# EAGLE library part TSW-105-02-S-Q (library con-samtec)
THROUGH-HOLE .025" SQ POST HEADER Source: Samtec TSW.pdf
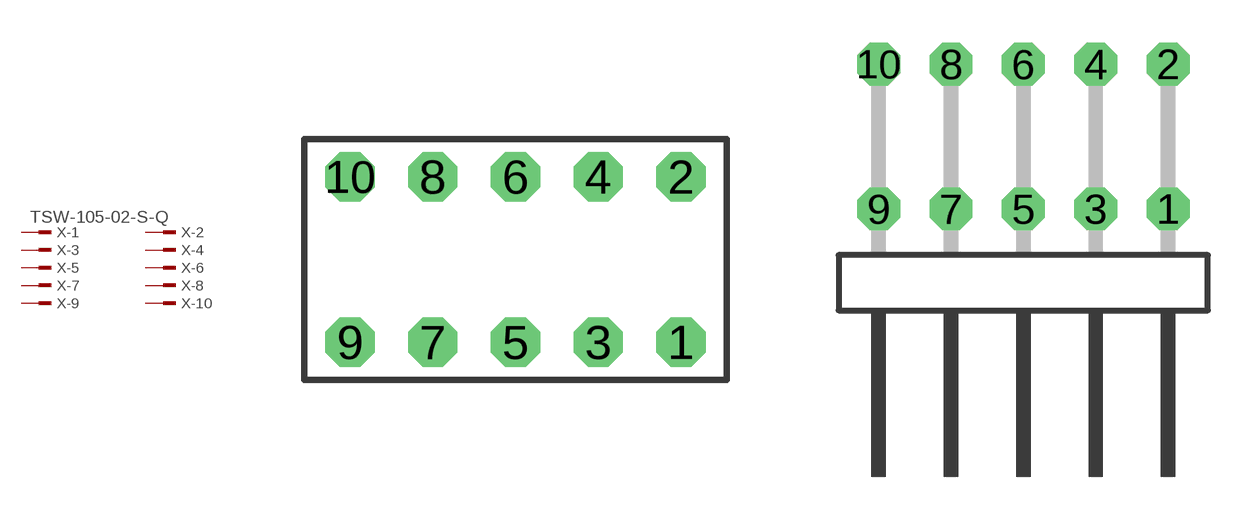
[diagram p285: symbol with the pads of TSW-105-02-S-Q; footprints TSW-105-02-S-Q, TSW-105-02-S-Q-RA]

Designator prefix X; gates -1=MPINV -2=MPIN -3=MPIN -4=MPIN -5=MPIN -6=MPIN -7=MPIN -8=MPIN -9=MPIN -10=MPIN

## TSW-105-02-S-Q (OC_FARNELL: unknown; OC_NEWARK: unknown)  [TSW-105-02-S-Q]
1  -1:1  pas
2  -2:1  pas
3  -3:1  pas
4  -4:1  pas
5  -5:1  pas
6  -6:1  pas
7  -7:1  pas
8  -8:1  pas
9  -9:1  pas
10  -10:1  pas

## TSW-105-02-S-Q-RA (OC_FARNELL: unknown; OC_NEWARK: unknown)  [TSW-105-02-S-Q-RA]
Pads as for TSW-105-02-S-Q

## Footprint TSW-105-02-S-Q (pad centres in mm)
THROUGH-HOLE .025" SQ POST HEADER Source: Samtec TSW.pdf
drill 1 pad 1.5 octagon: 1 5.08,-2.54; 2 5.08,2.54; 3 2.54,-2.54; 4 2.54,2.54; 5 0,-2.54; 6 0,2.54; 7 -2.54,-2.54; 8 -2.54,2.54; 9 -5.08,-2.54; 10 -5.08,2.54

## Footprint TSW-105-02-S-Q-RA (pad centres in mm)
THROUGH-HOLE .025" SQ POST HEADER Source: Samtec TSW.pdf
drill 1 pad 1.5 octagon: 1 5.08,1.524; 2 5.08,6.604; 3 2.54,1.524; 4 2.54,6.604; 5 0,1.524; 6 0,6.604; 7 -2.54,1.524; 8 -2.54,6.604; 9 -5.08,1.524; 10 -5.08,6.604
